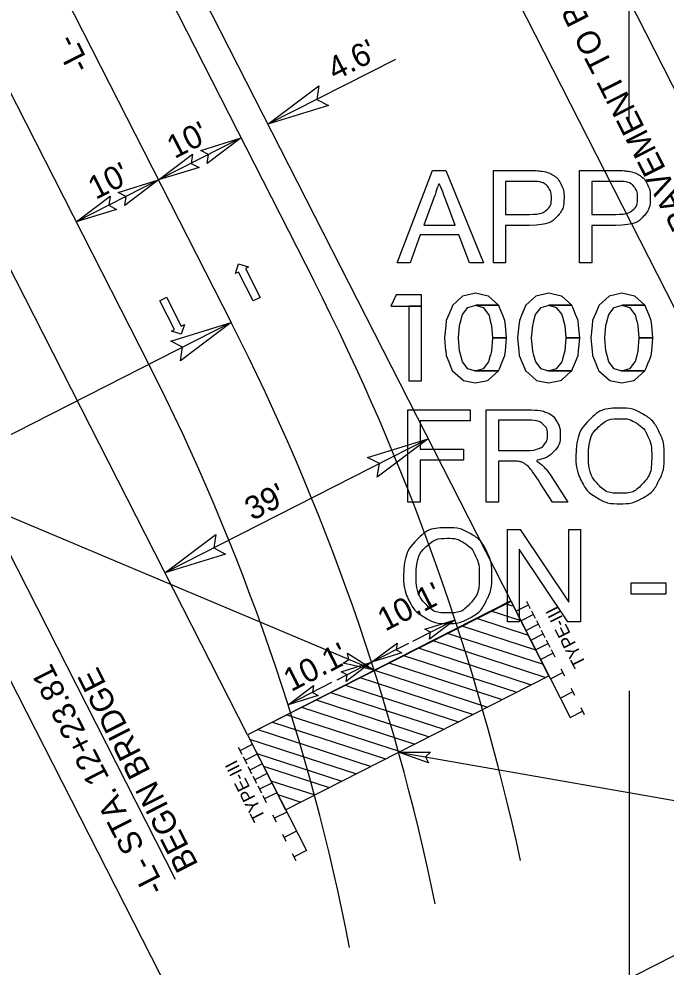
# Model space of a CAD drawing. Extents: x 557583 to 560285, y 513145 to 516544.
# Drawn here: x 558856.7 to 558996.5, y 515820.8 to 516025.9 of the extents above; entities that cross this region are included whole.
import ezdxf

# ---------------------------------------------------------------- set-up
doc = ezdxf.new("R2010")
doc.units = 0
for name, color, linetype in [('Default', 7, 'Continuous'), ('Exist Hydro Jurisdictional Stream or Body of Water NEU Mitigable Cogo Elevation', 7, 'Continuous'), ('Prop Approach Slab', 7, 'Continuous'), ('Prop Approach Slab Hatching', 7, 'Continuous'), ('Prop DSN Text', 7, 'Continuous'), ('Prop EOT', 7, 'Continuous'), ('Prop Lane Arrow CELL', 7, 'Continuous'), ('Prop Roadway Bridge', 7, 'Continuous'), ('Prop Structure Anchor Unit CELL', 7, 'Continuous'), ('Prop Terminator CELL', 7, 'Continuous'), ('Scratch_Level_0', 7, 'Continuous')]:
    doc.layers.add(name, color=color, linetype=linetype)

msp = doc.modelspace()

# ---------------------------------------------------------------- linework, layer by layer
at = {"layer": 'Default'}
for p, q in [((558988.6, 516003.66), (558988.6, 516457.65)), ((558988.6, 515880.54), (558988.6, 515457.65))]:
    msp.add_line(p, q, dxfattribs=at)
at = {"layer": 'Exist Hydro Jurisdictional Stream or Body of Water NEU Mitigable Cogo Elevation'}
msp.add_line((558829.57, 516103.63), (558902.55, 515960.27), dxfattribs=at)
msp.add_arc((558456.98, 515733.41), 500, 11.6635, 26.9819, dxfattribs=at)
at = {"layer": 'Prop Approach Slab'}
for p, q in [((558962.97, 515900.04), (558906.05, 515871.06)), ((558971.23, 515883.82), (558963.04, 515899.89)), ((558914.31, 515854.84), (558971.23, 515883.82)), ((558906.05, 515871.06), (558914.31, 515854.84))]:
    msp.add_line(p, q, dxfattribs=at)
at = {"layer": 'Prop Approach Slab Hatching'}
for p, q in [((558961.85, 515899.47), (558963.31, 515898.99)), ((558958.7, 515897.86), (558965.14, 515895.77)), ((558955.55, 515896.26), (558966.75, 515892.62)), ((558952.4, 515894.65), (558968.35, 515889.46)), ((558946.1, 515891.45), (558970.58, 515883.48)), ((558949.25, 515893.05), (558969.95, 515886.31)), ((558942.94, 515889.84), (558967.42, 515881.88)), ((558939.79, 515888.24), (558964.27, 515880.28)), ((558936.64, 515886.63), (558961.12, 515878.67)), ((558930.34, 515883.43), (558954.82, 515875.46)), ((558933.49, 515885.03), (558957.97, 515877.07)), ((558927.19, 515881.82), (558951.67, 515873.86)), ((558924.04, 515880.22), (558948.52, 515872.25)), ((558917.74, 515877.01), (558942.22, 515869.05)), ((558920.89, 515878.61), (558945.37, 515870.65)), ((558914.59, 515875.4), (558939.07, 515867.44)), ((558911.44, 515873.8), (558935.92, 515865.84)), ((558908.29, 515872.2), (558932.77, 515864.23)), ((558906.51, 515870.14), (558929.62, 515862.63)), ((558908.12, 515866.99), (558926.47, 515861.03)), ((558909.52, 515864.25), (558923.72, 515859.63)), ((558911.1, 515861.13), (558920.61, 515858.04)), ((558912.63, 515858.14), (558917.61, 515856.52))]:
    msp.add_line(p, q, dxfattribs=at)
at = {"layer": 'Prop DSN Text'}
for p, q in [((558938.04, 516017.14), (558910.49, 516003.11)), ((558904.69, 516000.16), (558886.86, 515991.09)), ((558886.86, 515991.09), (558869.04, 515982.01)), ((558902.55, 515960.27), (558842.27, 515929.58)), ((558945.13, 515935.08), (558888.21, 515906.1)), ((558933.45, 515885.01), (558849.38, 515920.49)), ((558849.38, 515920.49), (558890.46, 515839.82)), ((558950.93, 515895.92), (558941.74, 515891.24)), ((558940.9, 515890.82), (558932.89, 515886.74)), ((558932.89, 515886.74), (558925.36, 515882.9)), ((558924.25, 515882.34), (558914.83, 515877.54)), ((558938.73, 515867.27), (559037.29, 515850.07))]:
    msp.add_line(p, q, dxfattribs=at)
for points in [[(558879.66, 516196.55), (559055, 515852.15), (559074.16, 515861.9), (558898.81, 516206.31)], [(558879.66, 516196.55), (559055, 515852.15), (558908.44, 515777.53), (558733.09, 516121.93)]]:
    msp.add_lwpolyline(points, close=True, dxfattribs=at)
at = {"layer": 'Prop EOT'}
for p, q in [((558847.39, 516112.7), (558920.38, 515969.34)), ((558829.76, 516059.17), (558884.73, 515951.19))]:
    msp.add_line(p, q, dxfattribs=at)
for radius, start in [(520, 12.2663), (480, 11.0085)]:
    msp.add_arc((558456.98, 515733.41), radius, start, 26.9819, dxfattribs=at)
at = {"layer": 'Prop Lane Arrow CELL'}
for p, q in [((558903.47, 515970.82), (558904.14, 515972.93)), ((558904.14, 515972.93), (558906.28, 515972.25)), ((558906.28, 515972.25), (558905.61, 515971.91)), ((558905.61, 515971.91), (558908.78, 515965.67)), ((558904.14, 515971.16), (558903.47, 515970.82)), ((558907.31, 515964.92), (558904.14, 515971.16)), ((558887.12, 515964.94), (558888.59, 515965.69)), ((558888.59, 515965.69), (558891.76, 515959.45)), ((558908.78, 515965.67), (558907.31, 515964.92)), ((558890.29, 515958.71), (558887.12, 515964.94)), ((558891.76, 515959.45), (558892.43, 515959.79)), ((558892.43, 515959.79), (558891.76, 515957.69)), ((558889.62, 515958.37), (558890.29, 515958.71)), ((558891.76, 515957.69), (558889.62, 515958.37))]:
    msp.add_line(p, q, dxfattribs=at)
at = {"layer": 'Prop Roadway Bridge'}
for p, q in [((558879.31, 516064.35), (558963.04, 515899.89)), ((558906.05, 515871.06), (558822.39, 516035.37)), ((558963.04, 515899.89), (558906.04, 515871.07))]:
    msp.add_line(p, q, dxfattribs=at)
at = {"layer": 'Prop Structure Anchor Unit CELL'}
for p, q in [((558963.04, 515899.89), (558975.8, 515874.83)), ((558966.39, 515899.93), (558967.17, 515898.4)), ((558964.11, 515897.8), (558966.78, 515899.16)), ((558967.45, 515897.84), (558968.23, 515896.31)), ((558965.17, 515895.71), (558967.84, 515897.07)), ((558968.52, 515895.75), (558969.3, 515894.22)), ((558966.23, 515893.62), (558968.91, 515894.98)), ((558969.58, 515893.66), (558970.36, 515892.13)), ((558967.3, 515891.54), (558969.97, 515892.9)), ((558970.64, 515891.57), (558971.42, 515890.04)), ((558968.36, 515889.45), (558971.03, 515890.81)), ((558971.71, 515889.48), (558972.49, 515887.95)), ((558969.42, 515887.36), (558972.1, 515888.72)), ((558973.83, 515885.31), (558974.61, 515883.78)), ((558971.55, 515883.18), (558974.22, 515884.54)), ((558975.96, 515881.13), (558976.74, 515879.6)), ((558973.68, 515879), (558976.35, 515880.36)), ((558978.09, 515876.95), (558978.87, 515875.42)), ((558975.8, 515874.83), (558978.48, 515876.19)), ((558906.04, 515871.07), (558918.8, 515846.01)), ((558907.11, 515868.98), (558904.43, 515867.62)), ((558904.04, 515868.39), (558904.82, 515866.85)), ((558908.17, 515866.89), (558905.5, 515865.53)), ((558905.11, 515866.3), (558905.89, 515864.77)), ((558909.23, 515864.8), (558906.56, 515863.44)), ((558906.17, 515864.21), (558906.95, 515862.68)), ((558910.3, 515862.72), (558907.62, 515861.35)), ((558907.23, 515862.12), (558908.01, 515860.59)), ((558911.36, 515860.63), (558908.69, 515859.27)), ((558908.3, 515860.03), (558909.08, 515858.5)), ((558912.42, 515858.54), (558909.75, 515857.18)), ((558909.36, 515857.94), (558910.14, 515856.41)), ((558914.55, 515854.36), (558911.88, 515853)), ((558911.49, 515853.77), (558912.27, 515852.23)), ((558913.61, 515849.59), (558914.39, 515848.06)), ((558916.68, 515850.18), (558914, 515848.82)), ((558915.74, 515845.41), (558916.52, 515843.88)), ((558918.8, 515846.01), (558916.13, 515844.65))]:
    msp.add_line(p, q, dxfattribs=at)
at = {"layer": 'Prop Terminator CELL'}
for points in [[(558923.57, 516007.17), (558910.49, 516003.11), (558921.5, 516011.41), (558921.05, 516008.49)], [(558895.96, 515997.46), (558904.69, 516000.16), (558897.35, 515994.63), (558897.65, 515996.57)], [(558895.59, 515993.79), (558886.86, 515991.09), (558894.2, 515996.62), (558893.9, 515994.67)], [(558878.14, 515988.38), (558886.86, 515991.09), (558879.53, 515985.55), (558879.82, 515987.5)], [(558877.76, 515984.71), (558869.04, 515982.01), (558876.38, 515987.54), (558876.08, 515985.6)], [(558889.47, 515956.21), (558902.55, 515960.27), (558891.55, 515951.97), (558891.99, 515954.89)], [(558932.04, 515931.03), (558945.13, 515935.08), (558934.12, 515926.78), (558934.57, 515929.71)], [(558901.29, 515910.16), (558888.21, 515906.1), (558899.22, 515914.4), (558898.77, 515911.48)], [(558944.39, 515893.89), (558950.93, 515895.92), (558945.43, 515891.77), (558945.65, 515893.23)], [(558939.43, 515888.76), (558932.89, 515886.74), (558938.4, 515890.88), (558938.17, 515889.42)], [(558927.7, 515888.74), (558933.45, 515885.01), (558926.74, 515886.59), (558928, 515887.35)], [(558926.35, 515884.71), (558932.89, 515886.74), (558927.39, 515882.59), (558927.61, 515884.05)], [(558921.37, 515879.57), (558914.83, 515877.54), (558920.33, 515881.69), (558920.11, 515880.23)], [(558945.19, 515865), (558938.73, 515867.27), (558945.62, 515867.32), (558944.57, 515866.28)]]:
    msp.add_lwpolyline(points, close=True, dxfattribs=at)
at = {"layer": 'Scratch_Level_0'}
for points in [[(558938.39, 515973.13), (558946.08, 515993.13), (558948.94, 515993.13), (558957.11, 515973.13), (558954.09, 515973.13), (558951.78, 515979.18), (558943.39, 515979.18), (558941.2, 515973.13), (558938.39, 515973.13)], [(558959.22, 515973.13), (558959.22, 515993.13), (558966.76, 515993.13)], [(558977.86, 515973.13), (558977.86, 515993.13), (558985.41, 515993.13)], [(558966.99, 515990.77), (558961.87, 515990.77), (558961.87, 515983.62)], [(558985.63, 515990.77), (558980.51, 515990.77), (558980.51, 515983.62)], [(558946.37, 515987.21), (558944.16, 515981.33)], [(558944.16, 515981.33), (558950.95, 515981.33), (558948.85, 515986.89)], [(558961.87, 515983.62), (558967.04, 515983.62)], [(558980.51, 515983.62), (558985.68, 515983.62)], [(558967, 515981.26), (558961.87, 515981.26), (558961.87, 515973.13), (558959.22, 515973.13)], [(558985.64, 515981.26), (558980.51, 515981.26), (558980.51, 515973.13), (558977.86, 515973.13)], [(558940.71, 515921.36), (558940.71, 515941.36), (558954.22, 515941.36), (558954.22, 515939), (558943.36, 515939), (558943.36, 515932.81), (558952.75, 515932.81), (558952.75, 515930.45), (558943.36, 515930.45), (558943.36, 515921.36), (558940.71, 515921.36)], [(558957.69, 515921.36), (558957.69, 515941.36), (558966.56, 515941.36)], [(558966.67, 515939.15), (558960.34, 515939.15), (558960.34, 515932.54)], [(558960.34, 515932.54), (558966.03, 515932.54)], [(558963.41, 515930.25), (558960.34, 515930.25), (558960.34, 515921.36), (558957.69, 515921.36)], [(558971.84, 515926.81), (558975.3, 515921.36), (558971.99, 515921.36), (558969.35, 515925.52)], [(558962.3, 515895.48), (558962.3, 515915.48), (558965, 515915.48), (558975.53, 515899.77), (558975.53, 515915.48), (558978.06, 515915.48), (558978.06, 515895.48), (558975.35, 515895.48), (558964.83, 515911.19), (558964.83, 515895.48), (558962.3, 515895.48)], [(558988.97, 515901.48), (558988.97, 515903.95), (558996.53, 515903.95), (558996.53, 515901.48), (558988.97, 515901.48)]]:
    msp.add_lwpolyline(points, dxfattribs=at)
for points in [[(558938.24, 515966.2), (558937.05, 515963.77), (558943.7, 515963.77), (558943.7, 515966.2)], [(558952.69, 515947.71), (558955.35, 515947.17), (558957.95, 515947.71), (558958.09, 515947.74), (558960.3, 515949.77), (558955.31, 515949.77), (558955.18, 515949.8), (558955.12, 515949.82), (558953.72, 515950.22), (558952.56, 515951.73), (558952.56, 515951.74), (558952.55, 515951.74), (558952.19, 515953.08), (558952.18, 515953.11), (558951.91, 515954.08), (558951.9, 515954.14), (558951.66, 515956.83), (558951.66, 515956.87), (558951.66, 515956.9), (558951.9, 515959.59), (558952.17, 515960.61), (558952.18, 515960.64), (558952.53, 515961.95), (558952.55, 515961.99), (558953.72, 515963.51), (558955.22, 515963.91), (558955.27, 515963.92), (558955.41, 515963.96), (558960.35, 515963.96), (558958.17, 515965.95), (558958.06, 515965.97), (558955.38, 515966.56), (558955.38, 515966.56), (558952.61, 515965.97), (558952.58, 515965.95), (558950.43, 515963.96), (558950.39, 515963.92), (558950.38, 515963.91), (558950.21, 515963.51), (558949.59, 515961.99), (558949.57, 515961.95), (558949.03, 515960.64), (558949.02, 515960.61), (558948.92, 515959.59), (558948.63, 515956.9), (558948.63, 515956.87), (558948.63, 515956.83), (558948.9, 515954.14), (558948.91, 515954.08), (558949.01, 515953.11), (558949.01, 515953.08), (558949.56, 515951.74), (558949.57, 515951.73), (558950.18, 515950.22), (558950.34, 515949.82), (558950.35, 515949.8), (558950.39, 515949.77), (558952.66, 515947.74)], [(558968.51, 515947.71), (558971.17, 515947.17), (558973.76, 515947.71), (558973.91, 515947.74), (558976.12, 515949.77), (558971.13, 515949.77), (558971, 515949.8), (558970.93, 515949.82), (558969.54, 515950.22), (558968.38, 515951.73), (558968.37, 515951.74), (558968.37, 515951.74), (558968, 515953.08), (558968, 515953.11), (558967.73, 515954.08), (558967.72, 515954.14), (558967.48, 515956.83), (558967.48, 515956.87), (558967.48, 515956.9), (558967.72, 515959.59), (558967.99, 515960.61), (558968, 515960.64), (558968.35, 515961.95), (558968.36, 515961.99), (558969.54, 515963.51), (558971.04, 515963.91), (558971.09, 515963.92), (558971.23, 515963.96), (558976.16, 515963.96), (558973.99, 515965.95), (558973.88, 515965.97), (558971.2, 515966.56), (558971.2, 515966.56), (558968.42, 515965.97), (558968.4, 515965.95), (558966.25, 515963.96), (558966.21, 515963.92), (558966.19, 515963.91), (558966.03, 515963.51), (558965.4, 515961.99), (558965.39, 515961.95), (558964.85, 515960.64), (558964.84, 515960.61), (558964.74, 515959.59), (558964.45, 515956.9), (558964.45, 515956.87), (558964.45, 515956.83), (558964.72, 515954.14), (558964.73, 515954.08), (558964.83, 515953.11), (558964.83, 515953.08), (558965.38, 515951.74), (558965.39, 515951.73), (558966, 515950.22), (558966.16, 515949.82), (558966.17, 515949.8), (558966.21, 515949.77), (558968.47, 515947.74)], [(558984.33, 515947.71), (558986.99, 515947.17), (558989.58, 515947.71), (558989.73, 515947.74), (558991.93, 515949.77), (558986.95, 515949.77), (558986.82, 515949.8), (558986.75, 515949.82), (558985.36, 515950.22), (558984.19, 515951.73), (558984.19, 515951.74), (558984.19, 515951.74), (558983.82, 515953.08), (558983.82, 515953.11), (558983.55, 515954.08), (558983.53, 515954.14), (558983.3, 515956.83), (558983.3, 515956.87), (558983.3, 515956.9), (558983.53, 515959.59), (558983.81, 515960.61), (558983.82, 515960.64), (558984.17, 515961.95), (558984.18, 515961.99), (558985.36, 515963.51), (558986.86, 515963.91), (558986.91, 515963.92), (558987.05, 515963.96), (558991.98, 515963.96), (558989.81, 515965.95), (558989.69, 515965.97), (558987.02, 515966.56), (558987.02, 515966.56), (558984.24, 515965.97), (558984.22, 515965.95), (558982.06, 515963.96), (558982.02, 515963.92), (558982.01, 515963.91), (558981.85, 515963.51), (558981.22, 515961.99), (558981.2, 515961.95), (558980.67, 515960.64), (558980.66, 515960.61), (558980.56, 515959.59), (558980.27, 515956.9), (558980.27, 515956.87), (558980.27, 515956.83), (558980.54, 515954.14), (558980.55, 515954.08), (558980.65, 515953.11), (558980.65, 515953.08), (558981.2, 515951.74), (558981.2, 515951.73), (558981.82, 515950.22), (558981.98, 515949.82), (558981.99, 515949.8), (558982.03, 515949.77), (558984.29, 515947.74)], [(558940.91, 515963.77), (558940.91, 515947.65), (558943.7, 515947.65), (558943.7, 515963.77)], [(558958.84, 515959.59), (558959.06, 515956.9), (558962.08, 515956.9), (558961.82, 515959.59), (558961.72, 515960.61), (558961.71, 515960.64), (558961.71, 515960.64), (558961.18, 515961.95), (558961.18, 515961.95), (558961.16, 515961.99), (558960.55, 515963.51), (558960.55, 515963.51), (558960.39, 515963.91), (558960.39, 515963.92), (558960.35, 515963.96), (558955.41, 515963.96), (558955.54, 515963.92), (558955.59, 515963.91), (558957.01, 515963.51), (558958.17, 515961.99), (558958.21, 515961.95), (558958.56, 515960.64), (558958.56, 515960.61)], [(558974.66, 515959.59), (558974.87, 515956.9), (558977.9, 515956.9), (558977.64, 515959.59), (558977.54, 515960.61), (558977.53, 515960.64), (558977.52, 515960.64), (558977, 515961.95), (558977, 515961.95), (558976.98, 515961.99), (558976.37, 515963.51), (558976.37, 515963.51), (558976.21, 515963.91), (558976.21, 515963.92), (558976.16, 515963.96), (558971.23, 515963.96), (558971.36, 515963.92), (558971.4, 515963.91), (558972.82, 515963.51), (558973.99, 515961.99), (558974.02, 515961.95), (558974.37, 515960.64), (558974.38, 515960.61)], [(558990.47, 515959.59), (558990.69, 515956.9), (558993.72, 515956.9), (558993.46, 515959.59), (558993.36, 515960.61), (558993.35, 515960.64), (558993.34, 515960.64), (558992.82, 515961.95), (558992.82, 515961.95), (558992.8, 515961.99), (558992.19, 515963.51), (558992.19, 515963.51), (558992.03, 515963.91), (558992.02, 515963.92), (558991.98, 515963.96), (558987.05, 515963.96), (558987.18, 515963.92), (558987.22, 515963.91), (558988.64, 515963.51), (558989.81, 515961.99), (558989.84, 515961.95), (558990.19, 515960.64), (558990.2, 515960.61)], [(558955.45, 515949.8), (558955.31, 515949.77), (558960.3, 515949.77), (558960.34, 515949.8), (558960.36, 515949.82), (558960.52, 515950.22), (558961.14, 515951.73), (558961.15, 515951.74), (558961.7, 515953.08), (558961.72, 515953.11), (558961.81, 515954.08), (558961.82, 515954.14), (558962.08, 515956.83), (558962.09, 515956.87), (558962.08, 515956.9), (558959.05, 515956.9), (558959.05, 515956.87), (558959.05, 515956.83), (558958.83, 515954.14), (558958.83, 515954.08), (558958.57, 515953.11), (558958.56, 515953.08), (558958.2, 515951.74), (558958.19, 515951.73), (558957.01, 515950.22), (558955.52, 515949.82)], [(558971.26, 515949.8), (558971.13, 515949.77), (558976.12, 515949.77), (558976.16, 515949.8), (558976.18, 515949.82), (558976.34, 515950.22), (558976.96, 515951.73), (558976.97, 515951.74), (558977.52, 515953.08), (558977.53, 515953.11), (558977.63, 515954.08), (558977.63, 515954.14), (558977.9, 515956.83), (558977.9, 515956.87), (558977.9, 515956.9), (558974.87, 515956.9), (558974.87, 515956.87), (558974.87, 515956.83), (558974.65, 515954.14), (558974.65, 515954.08), (558974.39, 515953.11), (558974.38, 515953.08), (558974.02, 515951.74), (558974.01, 515951.73), (558972.82, 515950.22), (558971.33, 515949.82)], [(558987.08, 515949.8), (558986.95, 515949.77), (558991.93, 515949.77), (558991.97, 515949.8), (558991.99, 515949.82), (558992.16, 515950.22), (558992.78, 515951.73), (558992.79, 515951.74), (558993.34, 515953.08), (558993.35, 515953.11), (558993.45, 515954.08), (558993.45, 515954.14), (558993.72, 515956.83), (558993.72, 515956.87), (558993.72, 515956.9), (558990.69, 515956.9), (558990.69, 515956.87), (558990.69, 515956.83), (558990.47, 515954.14), (558990.47, 515954.08), (558990.2, 515953.11), (558990.2, 515953.08), (558989.84, 515951.74), (558989.82, 515951.73), (558988.64, 515950.22), (558987.15, 515949.82)]]:
    msp.add_lwpolyline(points, close=True, dxfattribs=at)
for points in [[(558966.76, 515993.13), (558968.76, 515993.13), (558969.81, 515992.94), (558971.28, 515992.69), (558972.28, 515992.01), (558973.28, 515991.32), (558973.88, 515990.07), (558974.49, 515988.83), (558974.49, 515987.34), (558974.49, 515984.79), (558972.87, 515983.02), (558971.24, 515981.26), (558967, 515981.26)], [(558985.41, 515993.13), (558987.4, 515993.13), (558988.45, 515992.94), (558989.93, 515992.69), (558990.92, 515992.01), (558991.92, 515991.32), (558992.53, 515990.07), (558993.13, 515988.83), (558993.13, 515987.34), (558993.13, 515984.79), (558991.51, 515983.02), (558989.89, 515981.26), (558985.64, 515981.26)], [(558948.85, 515986.89), (558947.91, 515989.41), (558947.44, 515991.03), (558947.05, 515989.11), (558946.37, 515987.21)], [(558967.04, 515983.62), (558969.61, 515983.62), (558970.68, 515984.57), (558971.76, 515985.53), (558971.76, 515987.26), (558971.76, 515988.52), (558971.13, 515989.41), (558970.49, 515990.3), (558969.46, 515990.59), (558968.79, 515990.77), (558966.99, 515990.77)], [(558985.68, 515983.62), (558988.25, 515983.62), (558989.33, 515984.57), (558990.41, 515985.53), (558990.41, 515987.26), (558990.41, 515988.52), (558989.77, 515989.41), (558989.14, 515990.3), (558988.1, 515990.59), (558987.43, 515990.77), (558985.63, 515990.77)], [(558966.56, 515941.36), (558969.24, 515941.36), (558970.63, 515940.82), (558972.02, 515940.29), (558972.85, 515938.92), (558973.68, 515937.56), (558973.68, 515935.91), (558973.68, 515933.78), (558972.31, 515932.32), (558970.93, 515930.86), (558968.05, 515930.46), (558969.1, 515929.96), (558969.65, 515929.47), (558970.81, 515928.4), (558971.84, 515926.81)], [(558977.04, 515931.1), (558977.04, 515936.08), (558979.71, 515938.9), (558982.39, 515941.71), (558986.62, 515941.71), (558989.39, 515941.71), (558991.61, 515940.39), (558993.83, 515939.07), (558995, 515936.7), (558996.17, 515934.34), (558996.17, 515931.34), (558996.17, 515928.3), (558994.94, 515925.9), (558993.71, 515923.5), (558991.46, 515922.26), (558989.21, 515921.03), (558986.6, 515921.03), (558983.78, 515921.03), (558981.55, 515922.39), (558979.33, 515923.75), (558978.18, 515926.11), (558977.04, 515928.47), (558977.04, 515931.1)], [(558966.03, 515932.54), (558967.85, 515932.54), (558968.87, 515932.91), (558969.89, 515933.29), (558970.42, 515934.11), (558970.95, 515934.94), (558970.95, 515935.91), (558970.95, 515937.32), (558969.92, 515938.24), (558968.9, 515939.15), (558966.67, 515939.15)], [(558979.77, 515931.07), (558979.77, 515927.46), (558981.71, 515925.38), (558983.65, 515923.3), (558986.59, 515923.3), (558989.58, 515923.3), (558991.51, 515925.4), (558993.44, 515927.5), (558993.44, 515931.36), (558993.44, 515933.8), (558992.61, 515935.62), (558991.79, 515937.44), (558990.2, 515938.44), (558988.61, 515939.44), (558986.63, 515939.44), (558983.82, 515939.44), (558981.79, 515937.51), (558979.77, 515935.58), (558979.77, 515931.07)], [(558969.35, 515925.52), (558968.19, 515927.33), (558967.44, 515928.28), (558966.69, 515929.24), (558966.09, 515929.62), (558965.5, 515930), (558964.89, 515930.15), (558964.44, 515930.25), (558963.41, 515930.25)], [(558939.78, 515905.22), (558939.78, 515910.2), (558942.45, 515913.01), (558945.13, 515915.83), (558949.36, 515915.83), (558952.13, 515915.83), (558954.35, 515914.51), (558956.58, 515913.18), (558957.74, 515910.82), (558958.91, 515908.45), (558958.91, 515905.45), (558958.91, 515902.41), (558957.68, 515900.01), (558956.46, 515897.61), (558954.2, 515896.38), (558951.95, 515895.14), (558949.35, 515895.14), (558946.52, 515895.14), (558944.3, 515896.51), (558942.07, 515897.87), (558940.93, 515900.23), (558939.78, 515902.59), (558939.78, 515905.22)], [(558942.51, 515905.19), (558942.51, 515901.57), (558944.45, 515899.49), (558946.4, 515897.41), (558949.33, 515897.41), (558952.32, 515897.41), (558954.25, 515899.51), (558956.18, 515901.61), (558956.18, 515905.47), (558956.18, 515907.91), (558955.36, 515909.73), (558954.53, 515911.55), (558952.94, 515912.56), (558951.35, 515913.56), (558949.37, 515913.56), (558946.56, 515913.56), (558944.54, 515911.63), (558942.51, 515909.7), (558942.51, 515905.19)]]:
    msp.add_open_spline(points, degree=3, dxfattribs=at)

# ---------------------------------------------------------------- texts
at = {"layer": 'Prop DSN Text'}
for s, rotation, p in [('DETAIL SHOWING PAVEMENT TO BRIDGE RELATIONSHIP', 116.9819, (559029.79, 515928.27)), ('-L-', 116.9819, (558872.25, 516015.7)), ("4.6'", 26.9819, (558925.01, 516012.48)), ("10'", 26.9819, (558890.3, 515995.57)), ("10'", 26.9819, (558873.26, 515986.73)), ("39'", 26.9819, (558907.12, 515917.3)), ("10.1'", 26.9819, (558935.83, 515893.36)), ("10.1'", 26.9819, (558915.5, 515880.3)), ('-L- STA. 12+23.81', 116.9819, (558888.44, 515837.89)), ('BEGIN BRIDGE', 116.9819, (558895.51, 515842.97))]:
    msp.add_text(s, height=5, rotation=rotation, dxfattribs=at).set_placement(p)
at = {"layer": 'Prop Structure Anchor Unit CELL'}
for p in [(558979.31, 515886.45), (558910.02, 515853.18)]:
    msp.add_text('TYPE-III', height=2.812, rotation=116.9819, dxfattribs=at).set_placement(p)

doc.saveas('drawing.dxf')
